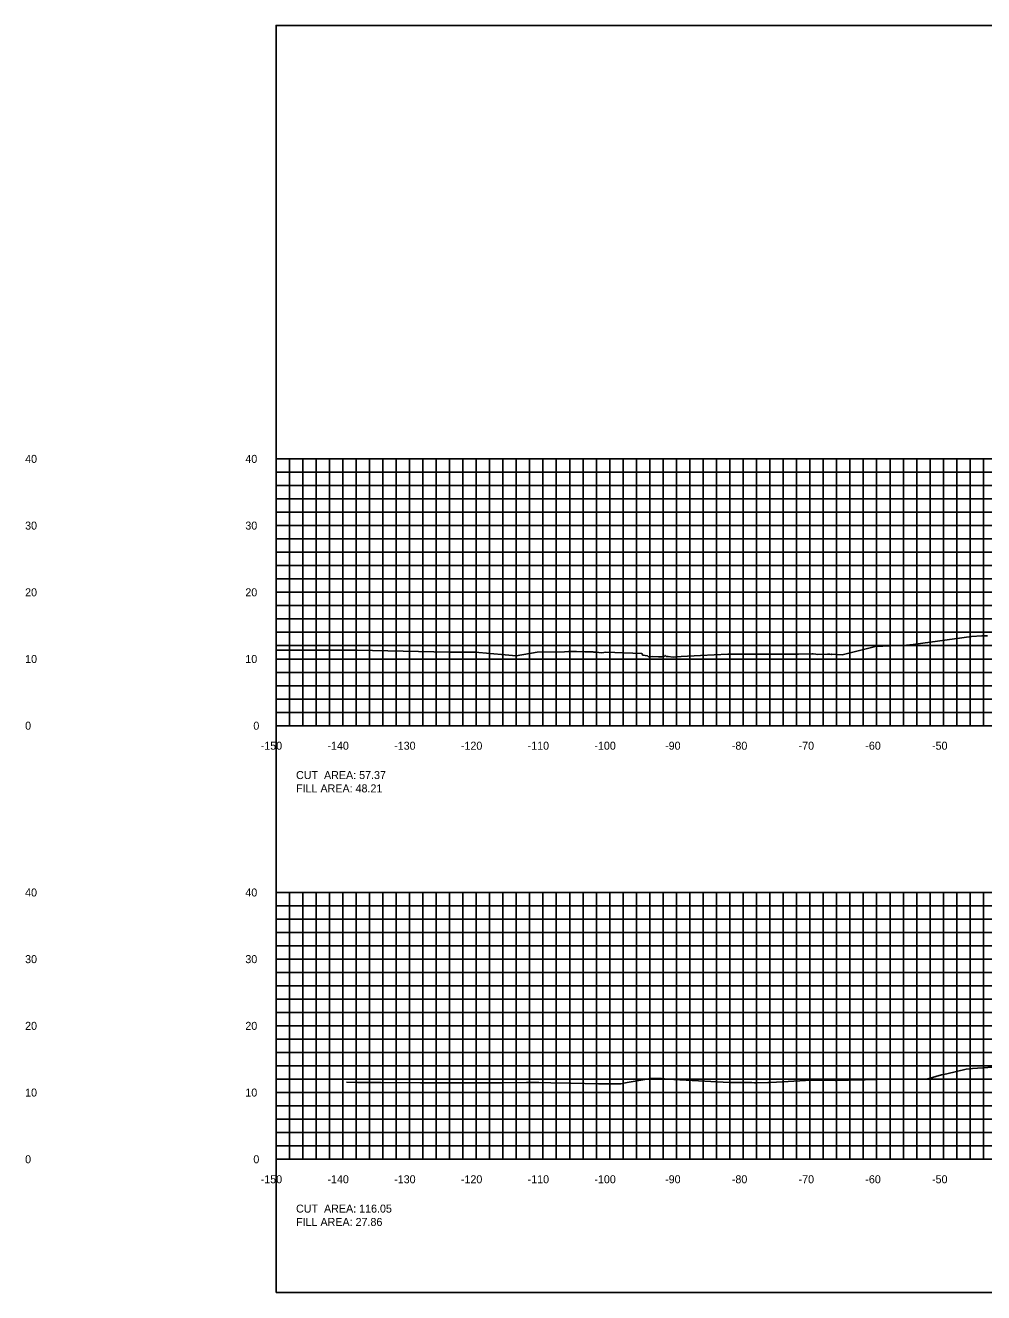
# Model space of a CAD drawing. Extents: x 1797652 to 1804159, y 242516 to 246906.
# Drawn here: x 1803476.9 to 1803620.5, y 242516 to 242706 of the extents above; entities that cross this region are included whole.
import ezdxf

# ---------------------------------------------------------------- set-up
doc = ezdxf.new("R2010")
doc.units = 0
for name, color, linetype in [('10', 7, 'Continuous'), ('31', 7, 'Continuous'), ('60', 7, 'Continuous'), ('Level 62', 7, 'Continuous'), ('M-ROADS', 7, 'Continuous')]:
    doc.layers.add(name, color=color, linetype=linetype)

msp = doc.modelspace()

# ---------------------------------------------------------------- linework, layer by layer
msp.add_lwpolyline([(1803514.49, 242516), (1803814.49, 242516), (1803814.49, 242706), (1803514.49, 242706)], close=True)
at = {"layer": '60'}
for p, q in [((1803514.43, 242641), (1803514.49, 242641)), ((1803514.49, 242601), (1803514.49, 242641)), ((1803514.43, 242631), (1803514.49, 242631)), ((1803514.43, 242621), (1803514.49, 242621)), ((1803514.43, 242611), (1803514.49, 242611)), ((1803514.43, 242601), (1803514.49, 242601)), ((1803514.49, 242601), (1803814.49, 242601)), ((1803514.49, 242600.94), (1803514.49, 242601)), ((1803524.49, 242600.94), (1803524.49, 242601)), ((1803534.49, 242600.94), (1803534.49, 242601)), ((1803544.49, 242600.94), (1803544.49, 242601)), ((1803554.49, 242600.94), (1803554.49, 242601)), ((1803564.49, 242600.94), (1803564.49, 242601)), ((1803574.49, 242600.94), (1803574.49, 242601)), ((1803584.49, 242600.94), (1803584.49, 242601)), ((1803594.49, 242600.94), (1803594.49, 242601)), ((1803604.49, 242600.94), (1803604.49, 242601)), ((1803614.49, 242600.94), (1803614.49, 242601)), ((1803514.43, 242576), (1803514.49, 242576)), ((1803514.49, 242536), (1803514.49, 242576)), ((1803514.43, 242566), (1803514.49, 242566)), ((1803514.43, 242556), (1803514.49, 242556)), ((1803514.43, 242546), (1803514.49, 242546)), ((1803514.43, 242536), (1803514.49, 242536)), ((1803514.49, 242536), (1803814.49, 242536)), ((1803514.49, 242535.94), (1803514.49, 242536)), ((1803524.49, 242535.94), (1803524.49, 242536)), ((1803534.49, 242535.94), (1803534.49, 242536)), ((1803544.49, 242535.94), (1803544.49, 242536)), ((1803554.49, 242535.94), (1803554.49, 242536)), ((1803564.49, 242535.94), (1803564.49, 242536)), ((1803574.49, 242535.94), (1803574.49, 242536)), ((1803584.49, 242535.94), (1803584.49, 242536)), ((1803594.49, 242535.94), (1803594.49, 242536)), ((1803604.49, 242535.94), (1803604.49, 242536)), ((1803614.49, 242535.94), (1803614.49, 242536))]:
    msp.add_line(p, q, dxfattribs=at)
at = {"layer": 'Level 62'}
for p, q in [((1803514.49, 242641), (1803814.49, 242641)), ((1803514.49, 242601), (1803514.49, 242641)), ((1803516.49, 242601), (1803516.49, 242641)), ((1803518.49, 242601), (1803518.49, 242641)), ((1803520.49, 242601), (1803520.49, 242641)), ((1803522.49, 242601), (1803522.49, 242641)), ((1803524.49, 242601), (1803524.49, 242641)), ((1803526.49, 242601), (1803526.49, 242641)), ((1803528.49, 242601), (1803528.49, 242641)), ((1803530.49, 242601), (1803530.49, 242641)), ((1803532.49, 242601), (1803532.49, 242641)), ((1803534.49, 242601), (1803534.49, 242641)), ((1803536.49, 242601), (1803536.49, 242641)), ((1803538.49, 242601), (1803538.49, 242641)), ((1803540.49, 242601), (1803540.49, 242641)), ((1803542.49, 242601), (1803542.49, 242641)), ((1803544.49, 242601), (1803544.49, 242641)), ((1803546.49, 242601), (1803546.49, 242641)), ((1803548.49, 242601), (1803548.49, 242641)), ((1803550.49, 242601), (1803550.49, 242641)), ((1803552.49, 242601), (1803552.49, 242641)), ((1803554.49, 242601), (1803554.49, 242641)), ((1803556.49, 242601), (1803556.49, 242641)), ((1803558.49, 242601), (1803558.49, 242641)), ((1803560.49, 242601), (1803560.49, 242641)), ((1803562.49, 242601), (1803562.49, 242641)), ((1803564.49, 242601), (1803564.49, 242641)), ((1803566.49, 242601), (1803566.49, 242641)), ((1803568.49, 242601), (1803568.49, 242641)), ((1803570.49, 242601), (1803570.49, 242641)), ((1803572.49, 242601), (1803572.49, 242641)), ((1803574.49, 242601), (1803574.49, 242641)), ((1803576.49, 242601), (1803576.49, 242641)), ((1803578.49, 242601), (1803578.49, 242641)), ((1803580.49, 242601), (1803580.49, 242641)), ((1803582.49, 242601), (1803582.49, 242641)), ((1803584.49, 242601), (1803584.49, 242641)), ((1803586.49, 242601), (1803586.49, 242641)), ((1803588.49, 242601), (1803588.49, 242641)), ((1803590.49, 242601), (1803590.49, 242641)), ((1803592.49, 242601), (1803592.49, 242641)), ((1803594.49, 242601), (1803594.49, 242641)), ((1803596.49, 242601), (1803596.49, 242641)), ((1803598.49, 242601), (1803598.49, 242641)), ((1803600.49, 242601), (1803600.49, 242641)), ((1803602.49, 242601), (1803602.49, 242641)), ((1803604.49, 242601), (1803604.49, 242641)), ((1803606.49, 242601), (1803606.49, 242641)), ((1803608.49, 242601), (1803608.49, 242641)), ((1803610.49, 242601), (1803610.49, 242641)), ((1803612.49, 242601), (1803612.49, 242641)), ((1803614.49, 242601), (1803614.49, 242641)), ((1803616.49, 242601), (1803616.49, 242641)), ((1803618.49, 242601), (1803618.49, 242641)), ((1803620.49, 242601), (1803620.49, 242641)), ((1803514.49, 242639), (1803814.49, 242639)), ((1803514.49, 242637), (1803814.49, 242637)), ((1803514.49, 242635), (1803814.49, 242635)), ((1803514.49, 242633), (1803814.49, 242633)), ((1803514.49, 242631), (1803814.49, 242631)), ((1803514.49, 242629), (1803814.49, 242629)), ((1803514.49, 242627), (1803814.49, 242627)), ((1803514.49, 242625), (1803814.49, 242625)), ((1803514.49, 242623), (1803814.49, 242623)), ((1803514.49, 242621), (1803814.49, 242621)), ((1803514.49, 242619), (1803814.49, 242619)), ((1803514.49, 242617), (1803814.49, 242617)), ((1803514.49, 242615), (1803814.49, 242615)), ((1803514.49, 242613), (1803814.49, 242613)), ((1803514.49, 242611), (1803814.49, 242611)), ((1803514.49, 242609), (1803814.49, 242609)), ((1803514.49, 242607), (1803814.49, 242607)), ((1803514.49, 242605), (1803814.49, 242605)), ((1803514.49, 242603), (1803814.49, 242603)), ((1803514.49, 242601), (1803814.49, 242601)), ((1803514.49, 242576), (1803814.49, 242576)), ((1803514.49, 242536), (1803514.49, 242576)), ((1803516.49, 242536), (1803516.49, 242576)), ((1803518.49, 242536), (1803518.49, 242576)), ((1803520.49, 242536), (1803520.49, 242576)), ((1803522.49, 242536), (1803522.49, 242576)), ((1803524.49, 242536), (1803524.49, 242576)), ((1803526.49, 242536), (1803526.49, 242576)), ((1803528.49, 242536), (1803528.49, 242576)), ((1803530.49, 242536), (1803530.49, 242576)), ((1803532.49, 242536), (1803532.49, 242576)), ((1803534.49, 242536), (1803534.49, 242576)), ((1803536.49, 242536), (1803536.49, 242576)), ((1803538.49, 242536), (1803538.49, 242576)), ((1803540.49, 242536), (1803540.49, 242576)), ((1803542.49, 242536), (1803542.49, 242576)), ((1803544.49, 242536), (1803544.49, 242576)), ((1803546.49, 242536), (1803546.49, 242576)), ((1803548.49, 242536), (1803548.49, 242576)), ((1803550.49, 242536), (1803550.49, 242576)), ((1803552.49, 242536), (1803552.49, 242576)), ((1803554.49, 242536), (1803554.49, 242576)), ((1803556.49, 242536), (1803556.49, 242576)), ((1803558.49, 242536), (1803558.49, 242576)), ((1803560.49, 242536), (1803560.49, 242576)), ((1803562.49, 242536), (1803562.49, 242576)), ((1803564.49, 242536), (1803564.49, 242576)), ((1803566.49, 242536), (1803566.49, 242576)), ((1803568.49, 242536), (1803568.49, 242576)), ((1803570.49, 242536), (1803570.49, 242576)), ((1803572.49, 242536), (1803572.49, 242576)), ((1803574.49, 242536), (1803574.49, 242576)), ((1803576.49, 242536), (1803576.49, 242576)), ((1803578.49, 242536), (1803578.49, 242576)), ((1803580.49, 242536), (1803580.49, 242576)), ((1803582.49, 242536), (1803582.49, 242576)), ((1803584.49, 242536), (1803584.49, 242576)), ((1803586.49, 242536), (1803586.49, 242576)), ((1803588.49, 242536), (1803588.49, 242576)), ((1803590.49, 242536), (1803590.49, 242576)), ((1803592.49, 242536), (1803592.49, 242576)), ((1803594.49, 242536), (1803594.49, 242576)), ((1803596.49, 242536), (1803596.49, 242576)), ((1803598.49, 242536), (1803598.49, 242576)), ((1803600.49, 242536), (1803600.49, 242576)), ((1803602.49, 242536), (1803602.49, 242576)), ((1803604.49, 242536), (1803604.49, 242576)), ((1803606.49, 242536), (1803606.49, 242576)), ((1803608.49, 242536), (1803608.49, 242576)), ((1803610.49, 242536), (1803610.49, 242576)), ((1803612.49, 242536), (1803612.49, 242576)), ((1803614.49, 242536), (1803614.49, 242576)), ((1803616.49, 242536), (1803616.49, 242576)), ((1803618.49, 242536), (1803618.49, 242576)), ((1803620.49, 242536), (1803620.49, 242576)), ((1803514.49, 242574), (1803814.49, 242574)), ((1803514.49, 242572), (1803814.49, 242572)), ((1803514.49, 242570), (1803814.49, 242570)), ((1803514.49, 242568), (1803814.49, 242568)), ((1803514.49, 242566), (1803814.49, 242566)), ((1803514.49, 242564), (1803814.49, 242564)), ((1803514.49, 242562), (1803814.49, 242562)), ((1803514.49, 242560), (1803814.49, 242560)), ((1803514.49, 242558), (1803814.49, 242558)), ((1803514.49, 242556), (1803814.49, 242556)), ((1803514.49, 242554), (1803814.49, 242554)), ((1803514.49, 242552), (1803814.49, 242552)), ((1803514.49, 242550), (1803814.49, 242550)), ((1803514.49, 242548), (1803814.49, 242548)), ((1803514.49, 242546), (1803814.49, 242546)), ((1803514.49, 242544), (1803814.49, 242544)), ((1803514.49, 242542), (1803814.49, 242542)), ((1803514.49, 242540), (1803814.49, 242540)), ((1803514.49, 242538), (1803814.49, 242538)), ((1803514.49, 242536), (1803814.49, 242536))]:
    msp.add_line(p, q, dxfattribs=at)
at = {"layer": 'M-ROADS'}
for points in [[(1803514.49, 242612.34), (1803515.27, 242612.33), (1803516.25, 242612.3), (1803516.85, 242612.3), (1803520.92, 242612.32), (1803521.18, 242612.32), (1803521.8, 242612.33), (1803523.54, 242612.33), (1803524.8, 242612.33), (1803525.85, 242612.33), (1803526.64, 242612.32), (1803540.45, 242612.04), (1803542.76, 242612.02), (1803544.32, 242612.01), (1803548.81, 242611.6), (1803550.47, 242611.49), (1803553.64, 242612.04), (1803557.73, 242612.09), (1803558.33, 242612.1), (1803558.62, 242612.1), (1803559.52, 242612.1), (1803560.76, 242612.09), (1803561.95, 242612.05), (1803562.11, 242612.03), (1803562.42, 242612.01), (1803563.32, 242611.94), (1803563.89, 242612.01), (1803569.29, 242611.8), (1803569.45, 242611.59), (1803570.17, 242611.47), (1803570.29, 242611.34), (1803570.83, 242611.38), (1803571.78, 242611.33), (1803572.29, 242611.34), (1803572.63, 242611.38), (1803572.78, 242611.53), (1803572.96, 242611.36), (1803573.25, 242611.36), (1803573.99, 242611.28), (1803575.22, 242611.39), (1803578.09, 242611.53), (1803582.19, 242611.7), (1803583.44, 242611.71), (1803584.6, 242611.7), (1803584.69, 242611.7), (1803584.71, 242611.7), (1803585.85, 242611.71), (1803587.2, 242611.7), (1803590.65, 242611.7), (1803592.78, 242611.7), (1803594.79, 242611.75), (1803594.96, 242611.75), (1803594.99, 242611.75), (1803595.39, 242611.7), (1803595.66, 242611.68), (1803597.14, 242611.71), (1803597.45, 242611.71), (1803597.67, 242611.69), (1803597.79, 242611.71), (1803598.43, 242611.67), (1803599.32, 242611.61), (1803604.13, 242612.83), (1803604.19, 242612.85), (1803604.2, 242612.85), (1803604.2, 242612.85), (1803608.98, 242613.06), (1803609.95, 242613.18), (1803618.7, 242614.37), (1803620.25, 242614.46), (1803621.12, 242614.46)], [(1803525.06, 242547.54), (1803526.69, 242547.51), (1803527.34, 242547.51), (1803529.4, 242547.51), (1803530.24, 242547.51), (1803536.14, 242547.48), (1803548.46, 242547.48), (1803552.02, 242547.49), (1803552.64, 242547.49), (1803553.86, 242547.49), (1803555.68, 242547.48), (1803558.66, 242547.42), (1803562.83, 242547.32), (1803563.96, 242547.32), (1803566.16, 242547.32), (1803567.12, 242547.49), (1803570.65, 242548.11), (1803571.71, 242548.11), (1803572.26, 242548.11), (1803573.17, 242548.03), (1803582.43, 242547.53), (1803583.43, 242547.49), (1803584.32, 242547.51), (1803585.38, 242547.53), (1803585.49, 242547.52), (1803585.77, 242547.5), (1803586.21, 242547.47), (1803586.4, 242547.46), (1803588.16, 242547.5), (1803588.35, 242547.5), (1803588.59, 242547.51), (1803594.75, 242547.84), (1803595.36, 242547.84), (1803595.85, 242547.84), (1803597.31, 242547.86), (1803597.65, 242547.85), (1803598.27, 242547.82), (1803598.33, 242547.82), (1803598.42, 242547.82), (1803600.28, 242547.85), (1803602.79, 242547.91), (1803605.89, 242548), (1803607.55, 242548.02), (1803607.84, 242548.02), (1803608.04, 242548.02), (1803608.47, 242548), (1803609.86, 242548.01), (1803610.02, 242548.01), (1803610.81, 242548.01), (1803611.27, 242548.01), (1803612.03, 242548), (1803614.21, 242548.67), (1803615.02, 242548.83), (1803617.92, 242549.52), (1803618.87, 242549.59), (1803621.88, 242549.82)]]:
    msp.add_lwpolyline(points, dxfattribs=at)

# ---------------------------------------------------------------- texts
at = {"layer": '10'}
for s, p in [('-150', (1803512.19, 242597.4)), ('-140', (1803522.19, 242597.4)), ('-130', (1803532.19, 242597.4)), ('-120', (1803542.19, 242597.4)), ('-110', (1803552.19, 242597.4)), ('-100', (1803562.19, 242597.4)), ('-90', (1803572.79, 242597.4)), ('-80', (1803582.79, 242597.4)), ('-70', (1803592.79, 242597.4)), ('-60', (1803602.79, 242597.4)), ('-50', (1803612.79, 242597.4)), ('CUT  AREA: 57.37', (1803517.49, 242593)), ('FILL AREA: 48.21', (1803517.49, 242591)), ('-150', (1803512.19, 242532.4)), ('-140', (1803522.19, 242532.4)), ('-130', (1803532.19, 242532.4)), ('-120', (1803542.19, 242532.4)), ('-110', (1803552.19, 242532.4)), ('-100', (1803562.19, 242532.4)), ('-90', (1803572.79, 242532.4)), ('-80', (1803582.79, 242532.4)), ('-70', (1803592.79, 242532.4)), ('-60', (1803602.79, 242532.4)), ('-50', (1803612.79, 242532.4)), ('CUT  AREA: 116.05', (1803517.49, 242528)), ('FILL AREA: 27.86', (1803517.49, 242526))]:
    msp.add_text(s, height=1.2, dxfattribs=at).set_placement(p)
at = {"layer": '31'}
for s, p in [('40', (1803476.89, 242640.4)), ('40', (1803509.89, 242640.4)), ('30', (1803476.89, 242630.4)), ('30', (1803509.89, 242630.4)), ('20', (1803476.89, 242620.4)), ('20', (1803509.89, 242620.4)), ('10', (1803476.89, 242610.4)), ('10', (1803509.89, 242610.4)), ('0', (1803476.89, 242600.4)), ('0', (1803511.09, 242600.4)), ('40', (1803476.89, 242575.4)), ('40', (1803509.89, 242575.4)), ('30', (1803476.89, 242565.4)), ('30', (1803509.89, 242565.4)), ('20', (1803476.89, 242555.4)), ('20', (1803509.89, 242555.4)), ('10', (1803476.89, 242545.4)), ('10', (1803509.89, 242545.4)), ('0', (1803476.89, 242535.4)), ('0', (1803511.09, 242535.4))]:
    msp.add_text(s, height=1.2, dxfattribs=at).set_placement(p)
at = {"layer": '60'}
for p in [(1803514.49, 242601), (1803514.49, 242536)]:
    msp.add_text('-', height=0.0001, dxfattribs=at).set_placement(p)

doc.saveas('drawing.dxf')
